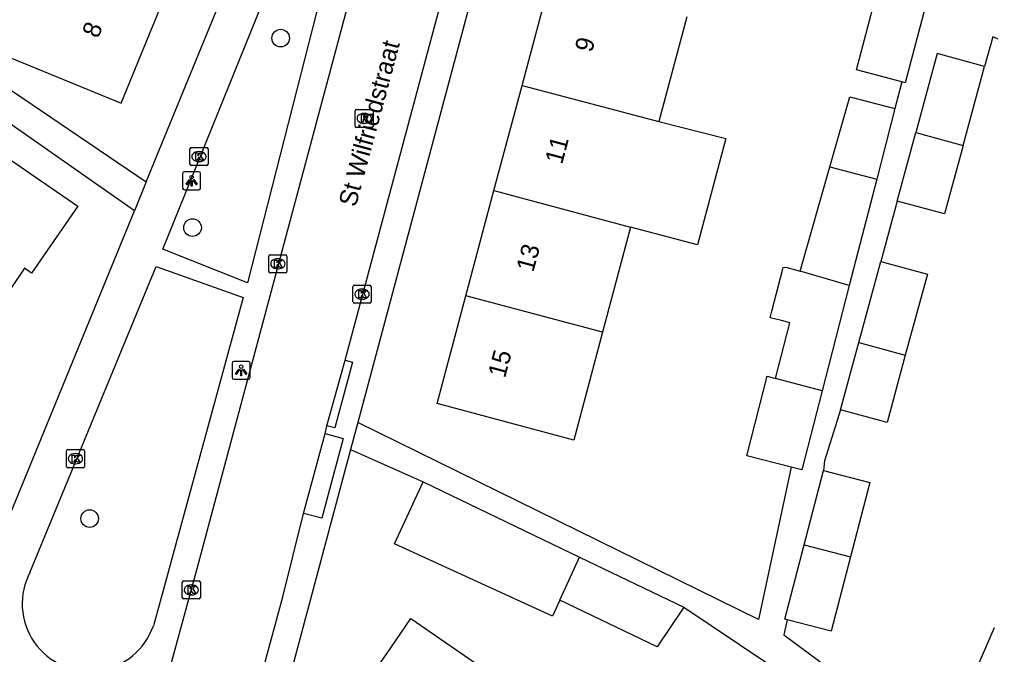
# Model space of a CAD drawing. Extents: x 162812 to 163818, y 381639 to 382470.
# Drawn here: x 163318.4 to 163372.2, y 381888.1 to 381923.4 of the extents above; entities that cross this region are included whole.
import ezdxf

# ---------------------------------------------------------------- set-up
doc = ezdxf.new("R2010")
doc.units = 0
for name, color, linetype in [('IMGEO_Boom', 7, 'Continuous'), ('IMGEO_Kolk', 7, 'Continuous'), ('IMGEO_Lichtpunt', 7, 'Continuous'), ('IMGEO_Openbare_ruimte_label', 7, 'Continuous'), ('IMGEO_Pand', 7, 'Continuous'), ('IMGEO_Pand_nummerreeks', 7, 'Continuous'), ('IMGEO_Rijbaan_lokaal_open', 7, 'Continuous'), ('IMGEO_Rioolput', 7, 'Continuous'), ('IMGEO_Voetpad_open', 7, 'Continuous')]:
    doc.layers.add(name, color=color, linetype=linetype)

msp = doc.modelspace()

# ---------------------------------------------------------------- linework, layer by layer
at = {"layer": 'IMGEO_Boom'}
for centre in [(163332.858, 381922.325), (163327.972, 381911.812), (163322.268, 381895.666)]:
    msp.add_circle(centre, 0.489, dxfattribs=at)
at = {"layer": 'IMGEO_Kolk'}
for p, q in [((163327.829, 381915.328), (163327.829, 381916.18)), ((163327.904, 381916.254), (163328.756, 381916.254)), ((163328.317, 381916.034), (163328.342, 381916.034)), ((163328.83, 381916.18), (163328.83, 381915.328)), ((163328.756, 381915.254), (163327.904, 381915.254)), ((163328.34, 381915.474), (163328.315, 381915.474)), ((163332.205, 381909.379), (163332.205, 381910.231)), ((163332.28, 381910.305), (163333.132, 381910.305)), ((163332.693, 381910.085), (163332.718, 381910.085)), ((163333.206, 381910.231), (163333.206, 381909.379)), ((163332.716, 381909.525), (163332.691, 381909.525)), ((163333.132, 381909.305), (163332.28, 381909.305)), ((163336.87, 381907.692), (163336.87, 381908.544)), ((163336.945, 381908.618), (163337.797, 381908.618)), ((163337.358, 381908.398), (163337.383, 381908.398)), ((163337.871, 381908.544), (163337.871, 381907.692)), ((163337.381, 381907.838), (163337.356, 381907.838)), ((163337.797, 381907.618), (163336.945, 381907.618)), ((163320.977, 381898.566), (163320.977, 381899.418)), ((163321.052, 381899.492), (163321.904, 381899.492)), ((163321.465, 381899.272), (163321.49, 381899.272)), ((163321.978, 381899.418), (163321.978, 381898.566)), ((163321.488, 381898.712), (163321.463, 381898.712)), ((163321.904, 381898.492), (163321.052, 381898.492)), ((163327.404, 381891.286), (163327.404, 381892.138)), ((163327.479, 381892.212), (163328.331, 381892.212)), ((163328.405, 381892.138), (163328.405, 381891.286)), ((163327.892, 381891.992), (163327.917, 381891.992)), ((163328.331, 381891.212), (163327.479, 381891.212)), ((163327.915, 381891.432), (163327.89, 381891.432))]:
    msp.add_line(p, q, dxfattribs=at)
for points in [[(163327.829, 381915.328), (163327.829, 381916.18)], [(163327.904, 381916.254), (163328.756, 381916.254)], [(163328.15, 381915.954), (163328.273, 381915.954), (163328.273, 381915.803), (163328.403, 381915.954), (163328.567, 381915.954), (163328.421, 381915.803), (163328.574, 381915.554), (163328.422, 381915.554), (163328.337, 381915.718), (163328.273, 381915.651), (163328.273, 381915.554), (163328.15, 381915.554), (163328.15, 381915.954)], [(163328.83, 381916.18), (163328.83, 381915.328)], [(163328.756, 381915.254), (163327.904, 381915.254)], [(163332.205, 381909.379), (163332.205, 381910.231)], [(163332.28, 381910.305), (163333.132, 381910.305)], [(163332.526, 381910.005), (163332.649, 381910.005), (163332.649, 381909.854), (163332.779, 381910.005), (163332.943, 381910.005), (163332.797, 381909.854), (163332.95, 381909.605), (163332.798, 381909.605), (163332.713, 381909.769), (163332.649, 381909.702), (163332.649, 381909.605), (163332.526, 381909.605), (163332.526, 381910.005)], [(163333.206, 381910.231), (163333.206, 381909.379)], [(163333.132, 381909.305), (163332.28, 381909.305)], [(163336.87, 381907.692), (163336.87, 381908.544)], [(163336.945, 381908.618), (163337.797, 381908.618)], [(163337.191, 381908.318), (163337.314, 381908.318), (163337.314, 381908.167), (163337.444, 381908.318), (163337.608, 381908.318), (163337.462, 381908.167), (163337.615, 381907.918), (163337.463, 381907.918), (163337.378, 381908.082), (163337.314, 381908.015), (163337.314, 381907.918), (163337.191, 381907.918), (163337.191, 381908.318)], [(163337.871, 381908.544), (163337.871, 381907.692)], [(163337.797, 381907.618), (163336.945, 381907.618)], [(163320.977, 381898.566), (163320.977, 381899.418)], [(163321.052, 381899.492), (163321.904, 381899.492)], [(163321.298, 381899.192), (163321.421, 381899.192), (163321.421, 381899.041), (163321.551, 381899.192), (163321.715, 381899.192), (163321.569, 381899.041), (163321.722, 381898.792), (163321.57, 381898.792), (163321.485, 381898.956), (163321.421, 381898.889), (163321.421, 381898.792), (163321.298, 381898.792), (163321.298, 381899.192)], [(163321.978, 381899.418), (163321.978, 381898.566)], [(163321.904, 381898.492), (163321.052, 381898.492)], [(163327.404, 381891.286), (163327.404, 381892.138)], [(163327.479, 381892.212), (163328.331, 381892.212)], [(163328.405, 381892.138), (163328.405, 381891.286)], [(163327.725, 381891.912), (163327.848, 381891.912), (163327.848, 381891.761), (163327.978, 381891.912), (163328.142, 381891.912), (163327.996, 381891.761), (163328.149, 381891.512), (163327.997, 381891.512), (163327.912, 381891.676), (163327.848, 381891.609), (163327.848, 381891.512), (163327.725, 381891.512), (163327.725, 381891.912)], [(163328.331, 381891.212), (163327.479, 381891.212)]]:
    msp.add_lwpolyline(points, dxfattribs=at)
for centre, start, end in [((163327.906, 381916.178), 91.552, 178.448), ((163327.906, 381916.178), 91.552, 178.448), ((163328.754, 381916.178), 1.552, 88.448), ((163328.754, 381916.178), 1.552, 88.448), ((163327.906, 381915.33), 181.552, 268.448), ((163327.906, 381915.33), 181.552, 268.448), ((163328.754, 381915.33), 271.552, 358.448), ((163328.754, 381915.33), 271.552, 358.448), ((163332.282, 381910.229), 91.552, 178.448), ((163332.282, 381910.229), 91.552, 178.448), ((163333.13, 381910.229), 1.552, 88.448), ((163333.13, 381910.229), 1.552, 88.448), ((163332.282, 381909.381), 181.552, 268.448), ((163332.282, 381909.381), 181.552, 268.448), ((163333.13, 381909.381), 271.552, 358.448), ((163333.13, 381909.381), 271.552, 358.448), ((163336.947, 381908.542), 91.552, 178.448), ((163336.947, 381908.542), 91.552, 178.448), ((163337.795, 381908.542), 1.552, 88.448), ((163337.795, 381908.542), 1.552, 88.448), ((163336.947, 381907.694), 181.552, 268.448), ((163336.947, 381907.694), 181.552, 268.448), ((163337.795, 381907.694), 271.552, 358.448), ((163337.795, 381907.694), 271.552, 358.448), ((163321.054, 381899.416), 91.552, 178.448), ((163321.054, 381899.416), 91.552, 178.448), ((163321.902, 381899.416), 1.552, 88.448), ((163321.902, 381899.416), 1.552, 88.448), ((163321.054, 381898.568), 181.552, 268.448), ((163321.054, 381898.568), 181.552, 268.448), ((163321.902, 381898.568), 271.552, 358.448), ((163321.902, 381898.568), 271.552, 358.448), ((163327.481, 381892.136), 91.552, 178.448), ((163327.481, 381892.136), 91.552, 178.448), ((163328.329, 381892.136), 1.552, 88.448), ((163328.329, 381892.136), 1.552, 88.448), ((163327.481, 381891.288), 181.552, 268.448), ((163327.481, 381891.288), 181.552, 268.448), ((163328.329, 381891.288), 271.552, 358.448), ((163328.329, 381891.288), 271.552, 358.448)]:
    msp.add_arc(centre, 0.0765, start, end, dxfattribs=at)
for centre, major_axis, ratio, start_param, end_param in [((163328.316, 381915.754), (-0.387, 0.002), 0.722429, 4.712389, 7.853982), ((163328.341, 381915.754), (-0.39, 0.002), 0.717154, 1.570796, 4.712389), ((163332.692, 381909.805), (-0.387, 0.002), 0.722429, 4.712389, 7.853982), ((163332.717, 381909.805), (-0.39, 0.002), 0.717154, 1.570796, 4.712389), ((163337.357, 381908.118), (-0.387, 0.002), 0.722429, 4.712389, 7.853982), ((163337.382, 381908.118), (-0.39, 0.002), 0.717154, 1.570796, 4.712389), ((163321.464, 381898.992), (-0.387, 0.002), 0.722429, 4.712389, 7.853982), ((163321.489, 381898.992), (-0.39, 0.002), 0.717154, 1.570796, 4.712389), ((163327.891, 381891.712), (-0.387, 0.002), 0.722429, 4.712389, 7.853982), ((163327.916, 381891.712), (-0.39, 0.002), 0.717154, 1.570796, 4.712389)]:
    msp.add_ellipse(centre, major_axis=major_axis, ratio=ratio, start_param=start_param, end_param=end_param, dxfattribs=at)
at = {"layer": 'IMGEO_Lichtpunt'}
for p, q in [((163327.424, 381914.813), (163327.424, 381914.006)), ((163327.424, 381914.813), (163327.424, 381914.006)), ((163328.326, 381914.908), (163327.518, 381914.908)), ((163328.326, 381914.908), (163327.518, 381914.908)), ((163328.42, 381914.006), (163328.42, 381914.813)), ((163328.42, 381914.006), (163328.42, 381914.813)), ((163327.518, 381913.912), (163328.326, 381913.912)), ((163327.518, 381913.912), (163328.326, 381913.912)), ((163330.17, 381904.297), (163330.17, 381903.49)), ((163330.17, 381904.297), (163330.17, 381903.49)), ((163331.072, 381904.392), (163330.264, 381904.392)), ((163331.072, 381904.392), (163330.264, 381904.392)), ((163331.166, 381903.49), (163331.166, 381904.297)), ((163331.166, 381903.49), (163331.166, 381904.297)), ((163330.264, 381903.396), (163331.072, 381903.396)), ((163330.264, 381903.396), (163331.072, 381903.396))]:
    msp.add_line(p, q, dxfattribs=at)
for points in [[(163327.798, 381914.477), (163327.837, 381914.449), (163327.649, 381914.187), (163327.611, 381914.214), (163327.798, 381914.477)], [(163327.9, 381914.429), (163327.947, 381914.429), (163327.947, 381914.107), (163327.9, 381914.107), (163327.9, 381914.429)], [(163328.01, 381914.449), (163328.048, 381914.476), (163328.235, 381914.214), (163328.196, 381914.186), (163328.01, 381914.449)], [(163330.544, 381903.961), (163330.583, 381903.933), (163330.395, 381903.671), (163330.357, 381903.698), (163330.544, 381903.961)], [(163330.756, 381903.933), (163330.794, 381903.96), (163330.981, 381903.698), (163330.942, 381903.67), (163330.756, 381903.933)], [(163330.646, 381903.913), (163330.693, 381903.913), (163330.693, 381903.591), (163330.646, 381903.591), (163330.646, 381903.913)]]:
    msp.add_lwpolyline(points, dxfattribs=at)
for centre in [(163327.923, 381914.611), (163330.669, 381904.095)]:
    msp.add_circle(centre, 0.0994, dxfattribs=at)
for centre, start, end in [((163327.518, 381914.813), 90, 180), ((163327.518, 381914.813), 90, 180), ((163328.326, 381914.813), 0, 90), ((163328.326, 381914.813), 0, 90), ((163327.518, 381914.006), 180, 270), ((163327.518, 381914.006), 180, 270), ((163328.326, 381914.006), 270, 0), ((163328.326, 381914.006), 270, 360), ((163330.264, 381904.297), 90, 180), ((163330.264, 381904.297), 90, 180), ((163331.072, 381904.297), 0, 90), ((163331.072, 381904.297), 0, 90), ((163330.264, 381903.49), 180, 270), ((163330.264, 381903.49), 180, 270), ((163331.072, 381903.49), 270, 0), ((163331.072, 381903.49), 270, 360)]:
    msp.add_arc(centre, 0.0946, start, end, dxfattribs=at)
at = {"layer": 'IMGEO_Pand'}
for points in [[(163318.773, 381927.579), (163316.169, 381928.645), (163313.815, 381922.896), (163316.419, 381921.83), (163319.38, 381920.618), (163324.007, 381918.723), (163326.361, 381924.472)], [(163346.247, 381919.701), (163347.804, 381925.536)], [(163367.306, 381919.896), (163364.795, 381920.557), (163365.853, 381924.577)], [(163365.853, 381924.577), (163365.933, 381924.881), (163368.632, 381924.17), (163367.494, 381919.847), (163367.306, 381919.896)], [(163355.377, 381923.515), (163353.825, 381917.699)], [(163371.895, 381920.756), (163369.271, 381921.469), (163368.08, 381917.086)], [(163370.704, 381916.373), (163371.895, 381920.756)], [(163344.689, 381913.865), (163346.247, 381919.701)], [(163346.247, 381919.701), (163353.825, 381917.699)], [(163363.312, 381915.193), (163364.412, 381919.075), (163366.922, 381918.428)], [(163311.057, 381914.819), (163313.615, 381918.52), (163318.955, 381914.83), (163321.613, 381912.993), (163319.046, 381909.279), (163318.645, 381909.556), (163311.926, 381899.566), (163306.613, 381903.239), (163309.457, 381907.353), (163311.314, 381910.04), (163313.092, 381908.811), (163315.245, 381911.924), (163311.057, 381914.819)], [(163366.922, 381918.428), (163365.912, 381914.506)], [(163353.825, 381917.699), (163357.548, 381916.765), (163355.972, 381910.858), (163352.263, 381911.843)], [(163367.047, 381913.285), (163368.08, 381917.086)], [(163368.08, 381917.086), (163370.704, 381916.373)], [(163370.704, 381916.373), (163369.671, 381912.572), (163367.047, 381913.285)], [(163361.67, 381909.398), (163363.312, 381915.193)], [(163363.312, 381915.193), (163365.912, 381914.506)], [(163365.912, 381914.506), (163364.392, 381908.605)], [(163343.132, 381908.028), (163344.689, 381913.865)], [(163344.689, 381913.865), (163352.263, 381911.843)], [(163352.263, 381911.843), (163350.706, 381906.007)], [(163364.92, 381905.433), (163366.145, 381909.938)], [(163366.145, 381909.938), (163368.722, 381909.238), (163367.497, 381904.733)], [(163360.296, 381903.448), (163361.093, 381906.532), (163360.639, 381906.65), (163360.001, 381906.815), (163360.093, 381907.176), (163360.702, 381909.529), (163360.72, 381909.598), (163360.872, 381909.608), (163361.67, 381909.398)], [(163364.392, 381908.605), (163361.67, 381909.398)], [(163364.392, 381908.605), (163362.886, 381902.757)], [(163350.706, 381906.007), (163349.11, 381900.027), (163341.536, 381902.048), (163343.132, 381908.028)], [(163350.706, 381906.007), (163343.132, 381908.028)], [(163363.907, 381901.704), (163364.92, 381905.433)], [(163364.92, 381905.433), (163367.497, 381904.733)], [(163367.497, 381904.733), (163366.484, 381901.003), (163363.907, 381901.704)], [(163361.168, 381898.522), (163358.704, 381899.156), (163359.843, 381903.569), (163360.296, 381903.448)], [(163362.886, 381902.757), (163360.296, 381903.448)], [(163362.886, 381902.757), (163361.756, 381898.37), (163361.168, 381898.522)], [(163361.892, 381894.212), (163362.961, 381898.339)], [(163362.961, 381898.339), (163365.524, 381897.675), (163364.455, 381893.548)], [(163348.342, 381891.147), (163347.932, 381890.252), (163339.179, 381894.263), (163340.753, 381897.698)], [(163340.753, 381897.698), (163349.433, 381893.528)], [(163360.952, 381890.051), (163360.822, 381890.085), (163361.892, 381894.212)], [(163361.892, 381894.212), (163364.455, 381893.548)], [(163348.342, 381891.147), (163349.433, 381893.528)], [(163349.433, 381893.528), (163355.208, 381890.754)], [(163364.455, 381893.548), (163363.386, 381889.421), (163360.952, 381890.051)], [(163355.208, 381890.754), (163353.733, 381888.558), (163348.342, 381891.147)], [(163339.455, 381878.257), (163334.335, 381881.785), (163338.961, 381888.5), (163340.075, 381890.117), (163345.195, 381886.59)], [(163383.437, 381884.818), (163380.883, 381878.932), (163376.297, 381880.923), (163373.361, 381882.197), (163369.875, 381883.71), (163372.439, 381889.62)]]:
    msp.add_lwpolyline(points, dxfattribs=at)
at = {"layer": 'IMGEO_Rijbaan_lokaal_open'}
for points in [[(163326.344, 381885.984), (163328.227, 381892.894), (163341.305, 381941.763), (163342.269, 381945.397), (163342.879, 381947.698), (163343.979, 381951.2), (163345.777, 381955.212), (163346.974, 381957.941)], [(163336.429, 381904.454), (163347.786, 381946.853), (163350.24, 381952.934), (163351.653, 381956.334)], [(163335.427, 381900.82), (163336.429, 381904.454)], [(163335.318, 381900.38), (163335.427, 381900.82)], [(163334.132, 381895.953), (163335.318, 381900.38)], [(163331.151, 381884.601), (163332.971, 381891.319), (163334.132, 381895.953)]]:
    msp.add_lwpolyline(points, dxfattribs=at)
at = {"layer": 'IMGEO_Rioolput'}
for p, q in [((163336.994, 381917.446), (163336.994, 381918.298)), ((163337.069, 381918.372), (163337.921, 381918.372)), ((163337.482, 381918.152), (163337.507, 381918.152)), ((163337.995, 381918.298), (163337.995, 381917.446)), ((163337.505, 381917.592), (163337.48, 381917.592)), ((163337.921, 381917.372), (163337.069, 381917.372))]:
    msp.add_line(p, q, dxfattribs=at)
for points in [[(163336.994, 381917.446), (163336.994, 381918.298)], [(163337.069, 381918.372), (163337.921, 381918.372)], [(163337.583, 381918.07), (163337.331, 381918.072), (163337.331, 381917.672)], [(163337.509, 381917.991), (163337.455, 381917.991), (163337.455, 381917.91)], [(163337.995, 381918.298), (163337.995, 381917.446)], [(163337.331, 381917.672), (163337.455, 381917.672), (163337.455, 381917.834), (163337.466, 381917.834)], [(163337.455, 381917.91), (163337.507, 381917.91)], [(163337.513, 381917.805), (163337.584, 381917.672), (163337.724, 381917.672), (163337.659, 381917.798)], [(163337.921, 381917.372), (163337.069, 381917.372)]]:
    msp.add_lwpolyline(points, dxfattribs=at)
for centre, radius, start, end in [((163337.071, 381918.296), 0.0765, 91.552, 178.448), ((163337.071, 381918.296), 0.0765, 91.552, 178.448), ((163337.515, 381917.895), 0.0964, 77.0061, 93.1865), ((163337.529, 381917.952), 0.0378, 276.6634, 79.6772), ((163337.582, 381917.96), 0.109, 350.3612, 89.416), ((163337.58, 381917.96), 0.112, 277.5842, 350.9817), ((163337.919, 381918.296), 0.0765, 1.552, 88.448), ((163337.919, 381918.296), 0.0765, 1.552, 88.448), ((163337.071, 381917.448), 0.0765, 181.552, 268.448), ((163337.071, 381917.448), 0.0765, 181.552, 268.448), ((163337.465, 381917.781), 0.0533, 26.0293, 88.6989), ((163337.491, 381918.099), 0.19, 274.7715, 282.9687), ((163337.564, 381917.745), 0.108, 29.5134, 73.7905), ((163337.919, 381917.448), 0.0765, 271.552, 358.448), ((163337.919, 381917.448), 0.0765, 271.552, 358.448)]:
    msp.add_arc(centre, radius, start, end, dxfattribs=at)
for centre, major_axis, ratio, start_param, end_param in [((163337.481, 381917.872), (-0.387, 0.002), 0.722429, 4.712389, 7.853982), ((163337.506, 381917.872), (-0.39, 0.002), 0.717154, 1.570796, 4.712389)]:
    msp.add_ellipse(centre, major_axis=major_axis, ratio=ratio, start_param=start_param, end_param=end_param, dxfattribs=at)
at = {"layer": 'IMGEO_Voetpad_open'}
for points in [[(163352.498, 381954.506), (163350.15, 381949.06), (163349.232, 381946.25), (163337.135, 381901.001)], [(163325.4, 381914.344), (163332.221, 381930.991), (163335.518, 381932.057), (163337.762, 381940.645)], [(163335.33, 381925.646), (163331.019, 381908.748), (163326.319, 381910.623), (163332.732, 381926.487)], [(163310.033, 381924.777), (163325.4, 381914.344)], [(163387.89, 381915.681), (163372.342, 381922.402), (163371.895, 381920.756)], [(163324.747, 381912.749), (163311.302, 381922.163)], [(163367.306, 381919.896), (163367.064, 381918.98), (163366.922, 381918.428)], [(163325.4, 381914.344), (163324.747, 381912.749)], [(163367.047, 381913.285), (163366.145, 381909.938)], [(163316.437, 381892.468), (163324.747, 381912.749)], [(163318.976, 381892.714), (163320.28, 381895.893), (163325.963, 381909.657), (163330.776, 381907.94)], [(163330.776, 381907.94), (163326.399, 381891.882), (163325.799, 381889.715)], [(163336.429, 381904.454), (163336.85, 381904.347), (163335.864, 381900.697), (163335.427, 381900.82)], [(163363.907, 381901.704), (163363.016, 381898.863), (163362.961, 381898.339)], [(163337.135, 381901.001), (163336.733, 381899.497)], [(163361.168, 381898.522), (163359.352, 381890.073), (163337.135, 381901.001)], [(163335.318, 381900.38), (163336.323, 381900.111), (163335.137, 381895.684), (163334.132, 381895.953)], [(163336.733, 381899.497), (163331.869, 381881.301), (163332.261, 381878.421)], [(163336.733, 381899.497), (163340.753, 381897.698)], [(163355.208, 381890.754), (163372.169, 381879.378)], [(163360.952, 381890.051), (163360.756, 381889.214), (163382.615, 381873.04)]]:
    msp.add_lwpolyline(points, dxfattribs=at)
msp.add_arc((163322.265, 381890.936), 3.739, 151.6058, 340.9392, dxfattribs=at)

# ---------------------------------------------------------------- texts
at = {"layer": 'IMGEO_Openbare_ruimte_label'}
msp.add_text('St Wilfriedstraat', height=1, rotation=74.9209, dxfattribs=at).set_placement((163337.022, 381912.912))
at = {"layer": 'IMGEO_Pand_nummerreeks'}
for s, rotation, p in [('8', 67.7351, (163322.734, 381922.267)), ('9', 75.0586, (163350.118, 381921.489)), ('11', 75.0586, (163348.462, 381915.282)), ('13', 75.0586, (163346.866, 381909.299)), ('15', 75.0586, (163345.299, 381903.427))]:
    msp.add_text(s, height=1, rotation=rotation, dxfattribs=at).set_placement(p)

doc.saveas('drawing.dxf')
